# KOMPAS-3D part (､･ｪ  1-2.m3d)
File: created 29.01.2016 13:47:21, last saved 25.07.2016 11:47:04.
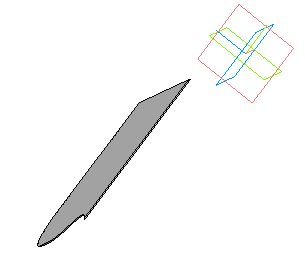
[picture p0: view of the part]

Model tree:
1. Эскиз:1
2. Операция выдавливания:1
     Толщина стенки 2 = 18; Расстояние 1 = 0.8
3. Эскиз:5
4. Вырезать элемент выдавливания:2
     Расстояние 1 = 10
5. Эскиз:6
6. Вырезать элемент выдавливания:3
     Расстояние 1 = 400
7. Эскиз:7
8. Вырезать элемент выдавливания:4
     Расстояние 1 = 400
